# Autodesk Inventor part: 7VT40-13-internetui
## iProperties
Created: 2010-01
Part Number: 7VT40-13-internetui
Document SubType Name: Modeling
Designer: Darius
Author: Darius
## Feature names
1. Base1
